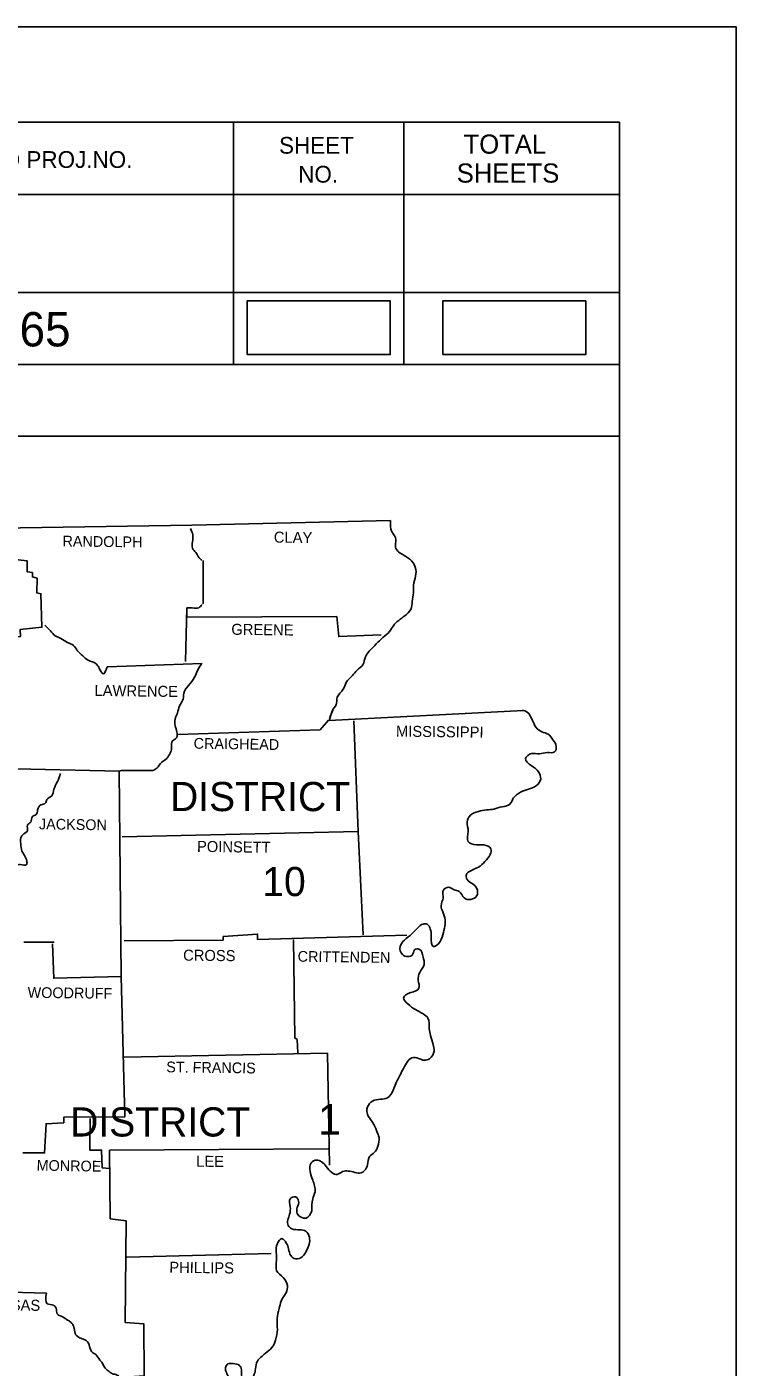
# Model space of a CAD drawing. Extents: x 1369979 to 1371646, y 379997 to 381064.
# Drawn here: x 1371501 to 1371645.6, y 380790.7 to 381064.1 of the extents above; entities that cross this region are included whole.
import ezdxf

# ---------------------------------------------------------------- set-up
doc = ezdxf.new("R2010")
doc.units = 0
for name, color, linetype in [('R_Border', 7, 'Continuous'), ('R_Draft', 7, 'Continuous'), ('R_No Plot', 7, 'Continuous')]:
    doc.layers.add(name, color=color, linetype=linetype)

msp = doc.modelspace()

# ---------------------------------------------------------------- linework, layer by layer
at = {"layer": 'R_Border'}
for p, q in [((1370040.95, 381044.6), (1371621.85, 381044.6)), ((1371543.15, 381044.6), (1371543.15, 380995.2)), ((1371577.85, 381044.6), (1371577.85, 380995.2)), ((1371621.85, 380017.3), (1371621.85, 381044.6)), ((1371621.85, 381029.9), (1371406.35, 381029.9)), ((1371621.85, 381030), (1371621.85, 381030)), ((1371621.85, 381009.9), (1371406.35, 381009.9)), ((1371421.15, 381009.9), (1371621.85, 381009.9)), ((1371621.85, 380995.2), (1371210.55, 380995.2)), ((1371406.35, 380980.6), (1371621.85, 380980.6))]:
    msp.add_line(p, q, dxfattribs=at)
at = {"layer": 'R_Draft'}
for p, q in [((1371562.65, 380922.62), (1371563.27, 380924.55)), ((1371562.8, 380923.25), (1371563.43, 380924.76)), ((1371500.42, 380877.41), (1371506.63, 380877.41))]:
    msp.add_line(p, q, dxfattribs=at)
for points in [[(1371545.95, 380997.25), (1371575.11, 380997.25), (1371575.11, 381008.19), (1371545.95, 381008.19)], [(1371585.8, 380997.25), (1371614.96, 380997.25), (1371614.96, 381008.19), (1371585.8, 381008.19)]]:
    msp.add_lwpolyline(points, close=True, dxfattribs=at)
for points in [[(1371288.78, 380960.99), (1371373.19, 380960.94), (1371447.27, 380961.09), (1371534.67, 380962.45), (1371575.18, 380963.39)], [(1371495.25, 380961.51), (1371495.09, 380960.26), (1371496.14, 380960.1), (1371496.09, 380959.48), (1371497.29, 380959.21), (1371497.39, 380958.38), (1371497.96, 380958.01), (1371498.12, 380955.51), (1371501.1, 380955.19), (1371501.1, 380952.95), (1371502.19, 380952.79), (1371502.19, 380951.91), (1371503.13, 380951.64), (1371503.08, 380948.62), (1371503.92, 380948.46), (1371504.13, 380941.62), (1371499.69, 380941.2), (1371499.74, 380939.74), (1371498.38, 380939.69), (1371498.85, 380912.75), (1371519.89, 380912.28), (1371520.26, 380870.41), (1371506.53, 380870.05), (1371506.27, 380877.1)], [(1371536.96, 380955.25), (1371536.96, 380946.42)], [(1371533.41, 380934.68), (1371533.67, 380945.59), (1371533.67, 380943.66), (1371564.21, 380943.81), (1371564.63, 380939.74), (1371573.25, 380940.06)], [(1371517.44, 380933.53), (1371536.81, 380934.21)], [(1371562.65, 380922.62), (1371602.27, 380924.65)], [(1371531.85, 380919.75), (1371560.82, 380920.69), (1371562.54, 380922.67)], [(1371567.66, 380922.57), (1371568.55, 380899.96), (1371569.59, 380878.92)], [(1371526.73, 380912.39), (1371520.36, 380912.39), (1371519.89, 380912.28)], [(1371568.55, 380899.96), (1371520.47, 380898.87)], [(1371520.88, 380877.72), (1371541.03, 380877.83), (1371541.09, 380878.56), (1371548.08, 380879.08), (1371548.08, 380877.98), (1371578.47, 380878.82)], [(1371555.39, 380877.98), (1371555.65, 380857.89), (1371556.12, 380857.57), (1371556.28, 380854.86)], [(1371555.39, 380877.98), (1371555.65, 380857.89), (1371556.12, 380857.57), (1371556.28, 380854.86)], [(1371555.39, 380877.98), (1371555.65, 380857.89), (1371556.12, 380857.57), (1371556.28, 380854.86)], [(1371555.39, 380877.98), (1371555.65, 380857.89), (1371556.12, 380857.57), (1371556.28, 380854.86)], [(1371555.39, 380877.98), (1371555.65, 380857.89), (1371556.12, 380857.57), (1371556.28, 380854.86)], [(1371520.26, 380870.41), (1371521.04, 380841.81), (1371508.61, 380841.75), (1371508.56, 380840.61), (1371504.96, 380840.4), (1371504.65, 380834.45), (1371500.26, 380834.45)], [(1371520.88, 380853.97), (1371562.33, 380854.81)], [(1371562.33, 380854.81), (1371562.75, 380831.94)], [(1371562.33, 380854.81), (1371562.75, 380831.94)], [(1371562.33, 380854.81), (1371562.75, 380831.94)], [(1371562.33, 380854.81), (1371562.75, 380831.94)], [(1371562.33, 380854.81), (1371562.75, 380831.94)], [(1371562.33, 380854.81), (1371562.75, 380831.94)], [(1371562.33, 380854.81), (1371562.75, 380831.94)], [(1371562.33, 380854.81), (1371562.75, 380831.94)], [(1371513.94, 380841.49), (1371513.89, 380835.02), (1371516.29, 380835.02), (1371516.39, 380831.42), (1371517.91, 380831.26)], [(1371520.88, 380788.71), (1371524.96, 380788.98), (1371524.9, 380799.57), (1371521.09, 380799.83), (1371521.3, 380820.56), (1371518.01, 380821.03), (1371517.91, 380834.97), (1371562.44, 380835.28)], [(1371521.41, 380813.2), (1371550.85, 380813.93)], [(1371505.06, 380805.84), (1371485.33, 380806.36), (1371485.23, 380799.94), (1371445.29, 380799.78)]]:
    msp.add_lwpolyline(points, dxfattribs=at)
for points in [[(1371575.18, 380963.39), (1371575.44, 380961.09), (1371576.17, 380959.89), (1371576.27, 380957.7), (1371577.16, 380956.76), (1371578.68, 380955.82), (1371580.03, 380954.31), (1371580.35, 380952.53), (1371579.93, 380950.71), (1371579.82, 380948.67), (1371579.61, 380946.89), (1371579.3, 380945.28), (1371578.05, 380943.97), (1371576.85, 380943.03), (1371575.75, 380941.93), (1371574.97, 380940.79), (1371573.61, 380939.53), (1371572.25, 380938.23), (1371571.16, 380937.08), (1371570.06, 380935.62), (1371569.54, 380934), (1371568.34, 380932.85), (1371567.4, 380931.81), (1371566.15, 380930.4), (1371565.52, 380928.99), (1371564.32, 380927.37), (1371564.06, 380925.8), (1371563.27, 380924.55), (1371563.22, 380924.34)], [(1371534.4, 380961.77), (1371534.87, 380960.47), (1371534.82, 380959.06), (1371534.82, 380957.75), (1371535.5, 380956.87), (1371536.18, 380955.77), (1371536.7, 380955.3)], [(1371536.75, 380946.27), (1371536.08, 380945.59), (1371534.77, 380945.59), (1371533.67, 380945.59)], [(1371504.7, 380942.09), (1371505.85, 380940.89), (1371506.84, 380939.9), (1371507.99, 380939.32), (1371509.35, 380938.54), (1371510.55, 380937.91), (1371511.33, 380936.92), (1371512.43, 380935.83), (1371513.52, 380934.94), (1371515.25, 380934.1), (1371515.82, 380933.22), (1371516.6, 380932.12), (1371517.44, 380933.53)], [(1371536.65, 380934.16), (1371535.87, 380932.9), (1371535.24, 380931.44), (1371533.99, 380929.77), (1371533.05, 380928.15), (1371532.89, 380927.06), (1371532.16, 380925.59), (1371531.74, 380924.13), (1371531.27, 380922.88), (1371531.27, 380921.57), (1371531.64, 380920.27), (1371531.53, 380919.07), (1371530.75, 380918.49), (1371530.54, 380916.98), (1371530.23, 380915.94), (1371529.55, 380914.89), (1371528.56, 380914.11), (1371527.51, 380912.91), (1371526.73, 380912.39)], [(1371601.7, 380924.6), (1371602.27, 380924.65), (1371604.05, 380922.78), (1371604.83, 380921.21), (1371605.98, 380920.32), (1371607.28, 380919.85), (1371608.28, 380918.65), (1371608.95, 380917.35), (1371608.59, 380916.2), (1371607.13, 380916.09), (1371605.51, 380915.83), (1371603.94, 380915.88), (1371602.69, 380914.84), (1371603.84, 380913.43), (1371605.35, 380912.13), (1371605.77, 380910.72), (1371604.93, 380909.36), (1371603.26, 380908.63), (1371601.65, 380908), (1371600.18, 380906.75), (1371599.51, 380905.55), (1371597.89, 380905.03), (1371596.22, 380904.56), (1371594.75, 380904.4), (1371593.08, 380904.09), (1371591.47, 380903.3), (1371590.79, 380901.95), (1371591, 380900.01), (1371590.94, 380897.98), (1371592.67, 380897.3), (1371594.18, 380897.25), (1371595.64, 380896.46), (1371595.49, 380895.32), (1371594.39, 380893.85), (1371593.08, 380892.71), (1371591.78, 380892.13), (1371590.58, 380891.04), (1371591, 380889.94), (1371592.09, 380889.21), (1371592.88, 380888.01), (1371592.77, 380886.91), (1371591.52, 380886.13), (1371590.16, 380886.44), (1371589.17, 380887.75), (1371588.02, 380888.16), (1371587.03, 380888.63), (1371585.88, 380887.96), (1371585.88, 380886.44), (1371585.46, 380884.82), (1371585.83, 380883.62), (1371586.3, 380881.95), (1371586.25, 380880.7), (1371585.83, 380878.92), (1371584.94, 380877.1), (1371583.9, 380876.52), (1371583.48, 380878.51), (1371583.27, 380880.12), (1371582.64, 380881.06), (1371581.81, 380881.12), (1371580.71, 380880.33), (1371579.51, 380879.13), (1371578, 380877.83), (1371577.11, 380876.52), (1371577.58, 380874.9), (1371578.73, 380874.49), (1371579.61, 380874.8), (1371580.08, 380875.84), (1371580.97, 380876), (1371581.81, 380874.38)], [(1371507.94, 380911.81), (1371507.31, 380910.19), (1371506.58, 380908.63), (1371506.11, 380907.27), (1371505.12, 380906.49), (1371504.8, 380905.76), (1371503.92, 380905.44), (1371503.24, 380904.4), (1371502.92, 380903.46), (1371502.19, 380903.04), (1371501.83, 380901.89), (1371501.15, 380901.27), (1371501.2, 380900.22), (1371500.42, 380899.49), (1371499.79, 380898.66), (1371499.79, 380897.51), (1371500.05, 380895.99), (1371500.58, 380895.11), (1371501.05, 380893.96), (1371500.99, 380893.23), (1371499.69, 380893.23), (1371498.59, 380893.02)], [(1371581.81, 380874.38), (1371582.02, 380872.87), (1371581.13, 380871.25), (1371580.82, 380869.63), (1371580.97, 380868.01), (1371579.3, 380867.13), (1371577.84, 380866.08), (1371578.68, 380864.83), (1371580.24, 380863.68), (1371581.81, 380862.79), (1371582.8, 380861.9), (1371583.06, 380859.76), (1371583.32, 380858.41), (1371583.84, 380856.53), (1371584.05, 380855.22), (1371583.11, 380853.66), (1371582.02, 380853.34), (1371580.87, 380853.71), (1371579.51, 380853.81), (1371578.41, 380852.77), (1371577.63, 380851.31), (1371576.85, 380849.85), (1371576.27, 380848.59), (1371575.7, 380847.24), (1371574.55, 380845.67), (1371573.14, 380845.41), (1371571.47, 380844.99), (1371570.48, 380843.84), (1371570.64, 380841.91), (1371571.58, 380840.61), (1371572.31, 380838.99), (1371572.83, 380837.58), (1371572.57, 380835.8), (1371571.84, 380834.5), (1371570.9, 380833.71), (1371570.48, 380832.04), (1371569.8, 380830.79), (1371569.17, 380830.37), (1371567.92, 380830.48), (1371566.56, 380830.74), (1371565.41, 380830.63), (1371564.32, 380830.06), (1371563.22, 380830.43), (1371562.07, 380831.68), (1371561.13, 380832.62), (1371560.09, 380832.98), (1371558.99, 380832.41), (1371558.78, 380830.69), (1371559.31, 380828.91), (1371559.78, 380826.51), (1371559.31, 380825.05), (1371559.15, 380822.65)], [(1371559.15, 380822.65), (1371557.95, 380821.13), (1371556.17, 380822.07), (1371556.17, 380823.33), (1371556.44, 380824.63), (1371555.81, 380825.47), (1371554.71, 380825.1), (1371554.71, 380823.48), (1371554.61, 380821.92), (1371554.3, 380819.67), (1371555.03, 380818.99), (1371556.7, 380818.78), (1371557.9, 380818.47), (1371558.63, 380817.27), (1371558.58, 380815.81), (1371558, 380814.4), (1371557.17, 380813.25), (1371555.86, 380812.83), (1371554.82, 380813.51), (1371554.4, 380814.87), (1371553.93, 380816.07), (1371553.04, 380816.96), (1371552.1, 380815.96), (1371551.89, 380814.14), (1371551.95, 380812.57), (1371551.95, 380810.43), (1371553.3, 380809.02), (1371554.14, 380807.4), (1371553.88, 380805.94), (1371552.89, 380804.22), (1371552.47, 380802.7), (1371552.05, 380800.67), (1371552.1, 380798.42), (1371551.74, 380796.23), (1371551.01, 380794.77), (1371549.65, 380793.57), (1371548.76, 380792.79), (1371548.03, 380792), (1371547.66, 380790.44), (1371547.4, 380789.34), (1371546.41, 380788.04), (1371545.63, 380787.93), (1371545, 380788.45), (1371544.79, 380789.34), (1371544.79, 380790.23), (1371544.38, 380791.12), (1371543.07, 380791.48), (1371542.03, 380791.43), (1371541.56, 380790.7), (1371542.24, 380788.66), (1371542.5, 380787.36), (1371542.13, 380785.58), (1371542.34, 380785.37), (1371540.46, 380784.38), (1371538.95, 380784.22), (1371537.69, 380783.86), (1371536.49, 380783.08), (1371535.92, 380781.93), (1371535.08, 380780.99), (1371534.35, 380780.1), (1371533.36, 380779.68), (1371532.26, 380779.89), (1371530.8, 380780.05), (1371529.97, 380779), (1371530.23, 380777.49), (1371531.22, 380776.6), (1371532.68, 380776.18), (1371534.2, 380776.29), (1371535.66, 380776.45), (1371537.01, 380775.72), (1371536.75, 380774.31), (1371535.45, 380773.63), (1371533.52, 380773.42), (1371531.95, 380773.57), (1371530.07, 380773.16), (1371529.13, 380771.96), (1371529.65, 380770.13), (1371531.69, 380769.4), (1371532.63, 380767.68), (1371532.68, 380766.06), (1371532, 380763.92), (1371531.06, 380762.92), (1371529.24, 380762.51), (1371527.83, 380762.25), (1371527.62, 380759.84), (1371526.99, 380758.64), (1371525.9, 380758.28), (1371524.33, 380759.06), (1371523.39, 380759.43), (1371522.24, 380759.95), (1371520.78, 380760.84), (1371519.68, 380760.68), (1371520, 380758.38), (1371520.1, 380758.28), (1371521.35, 380756.56), (1371522.61, 380755.2), (1371523.18, 380753.58)], [(1371505.06, 380805.84), (1371505.22, 380803.7), (1371506.47, 380803.38), (1371507, 380802.81), (1371507.26, 380801.61), (1371508.15, 380801.09), (1371509.35, 380800.36), (1371510.08, 380799.83), (1371510.6, 380799), (1371510.91, 380797.64), (1371511.75, 380796.75), (1371512.9, 380796.34), (1371513.73, 380795.34), (1371514.25, 380793.93), (1371515.09, 380793.31), (1371515.92, 380792.21), (1371516.34, 380791.74), (1371517.07, 380790.49), (1371517.8, 380789.86), (1371518.33, 380789.5), (1371519.16, 380789.24), (1371520.2, 380788.56), (1371520.88, 380787.51), (1371520.88, 380786.73), (1371520.62, 380785.53), (1371520.41, 380784.28), (1371520.31, 380782.87), (1371520.2, 380781.61), (1371520.67, 380780.57), (1371520.41, 380779), (1371519.89, 380778.17), (1371519.84, 380777.02), (1371519.68, 380775.3), (1371519.47, 380774.31), (1371519, 380772.69), (1371518.33, 380771.85)]]:
    msp.add_spline(points, degree=3, dxfattribs=at)
at = {"layer": 'R_No Plot'}
msp.add_line((1369978.95, 381064.07), (1371645.61, 381064.07), dxfattribs=at)
msp.add_lwpolyline([(1369978.91, 381064.07), (1371645.61, 381064.07), (1371645.61, 379997.39), (1369978.91, 379997.39)], close=True, dxfattribs=at)

# ---------------------------------------------------------------- texts
at = {"layer": 'R_Border'}
for s, height, p in [('SHEET', 3.42, (1371552.45, 381038.2)), ('TOTAL', 3.91, (1371590.05, 381038.2)), ('FED.AID PROJ.NO.', 3.42, (1371481.65, 381035.3)), ('SHEETS', 3.91, (1371588.65, 381032.3)), ('NO.', 3.42, (1371556.35, 381032.3)), ('070265', 7, (1371478.73, 380998.9))]:
    msp.add_text(s, height=height, dxfattribs=at).set_placement(p)
at = {"layer": 'R_Draft'}
for s, height, rotation, p in [('RANDOLPH', 2.193, 359.2584, (1371508.3, 380958.12)), ('CLAY', 2.245, 359.2258, (1371551.37, 380958.9)), ('GREENE', 2.245, 359.2361, (1371542.71, 380940.11)), ('LAWRENCE', 2.245, 359.2678, (1371514.83, 380927.63)), ('MISSISSIPPI', 2.2445, 359.3097, (1371576.27, 380919.33)), ('CRAIGHEAD', 2.193, 359.1159, (1371535.03, 380916.88)), ('JACKSON', 2.192, 359.1352, (1371503.5, 380900.43)), ('POINSETT', 2.245, 359.1987, (1371535.71, 380895.84)), ('CROSS', 2.245, 359.384, (1371532.89, 380873.65)), ('CRITTENDEN', 2.193, 359.213, (1371556.23, 380873.44)), ('WOODRUFF', 2.192, 359.2748, (1371501.2, 380866.08)), ('ST. FRANCIS', 2.1922, 359.2216, (1371529.45, 380850.89)), ('LEE', 2.245, 359.4327, (1371535.55, 380831.63)), ('MONROE', 2.192, 359.0331, (1371503.03, 380830.84)), ('PHILLIPS', 2.245, 359.318, (1371530.07, 380810.01)), ('ARKANSAS', 2.245, 359.2678, (1371487.42, 380802.44))]:
    msp.add_text(s, height=height, rotation=rotation, dxfattribs=at).set_placement(p)
for s, height, p in [('DISTRICT', 5.951, (1371530.23, 380904.14)), ('10', 5.951, (1371549.04, 380886.81)), ('DISTRICT', 5.951, (1371509.87, 380837.79)), ('1', 6.26, (1371560.4, 380838.15))]:
    msp.add_text(s, height=height, dxfattribs=at).set_placement(p)

doc.saveas('drawing.dxf')
